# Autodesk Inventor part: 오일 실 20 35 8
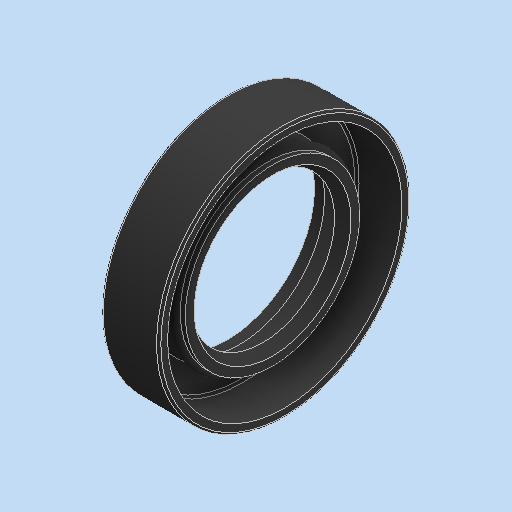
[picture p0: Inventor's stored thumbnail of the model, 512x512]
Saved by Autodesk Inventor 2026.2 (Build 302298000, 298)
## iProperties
Created: 2026-01
Part Number: 오일 실 20 35 8
Material: 고무
Description: 오일-실
Document SubType Name: Modeling
Designer: PC2-07
Density: 0.93 g/cm^3
Appearance: 기본값
Author: jhkim
Sending System: Autodesk Inventor 2026
Preprocessor: ST-DEVELOPER v20.1
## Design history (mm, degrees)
feature "Solid1"
node "솔리드1"
